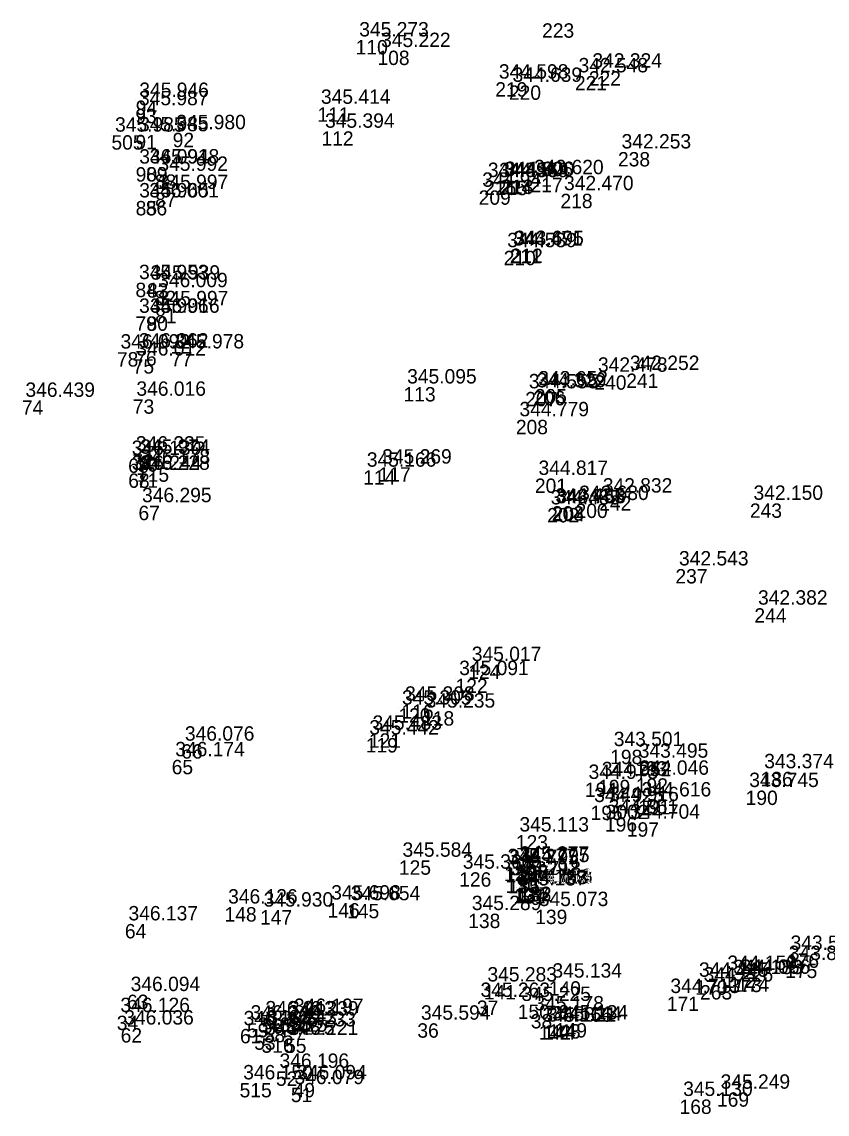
# Model space of a CAD drawing. Extents: x -829398 to -819400, y -1074439 to -1067977.
# Drawn here: x -820131.9 to -820064.8, y -1073098.9 to -1073007.8 of the extents above; entities that cross this region are included whole.
import ezdxf

# ---------------------------------------------------------------- set-up
doc = ezdxf.new("R2010")
doc.units = 0
doc.layers.add('Vrstva 60', color=7, linetype='Continuous')
doc.layers.add('Vrstva 61', color=7, linetype='Continuous')

msp = doc.modelspace()

# ---------------------------------------------------------------- linework, layer by layer
at = {"layer": 'Vrstva 60'}
for p, q in [((-820088.534, -1073007.916), (-820088.534, -1073007.916)), ((-820104.087, -1073009.31), (-820104.087, -1073009.31)), ((-820102.266, -1073010.196), (-820102.266, -1073010.196)), ((-820085.791, -1073012.306), (-820085.791, -1073012.306)), ((-820084.637, -1073011.912), (-820084.637, -1073011.912)), ((-820092.439, -1073012.828), (-820092.439, -1073012.828)), ((-820091.299, -1073013.099), (-820091.299, -1073013.099)), ((-820122.464, -1073015.051), (-820122.464, -1073015.051)), ((-820122.435, -1073014.36), (-820122.435, -1073014.36)), ((-820107.283, -1073014.933), (-820107.283, -1073014.933)), ((-820119.351, -1073017.052), (-820119.351, -1073017.052)), ((-820106.94, -1073016.929), (-820106.94, -1073016.929)), ((-820124.459, -1073017.256), (-820124.459, -1073017.256)), ((-820122.459, -1073017.222), (-820122.459, -1073017.222)), ((-820082.202, -1073018.659), (-820082.202, -1073018.659)), ((-820122.439, -1073019.92), (-820122.439, -1073019.92)), ((-820121.569, -1073019.908), (-820121.569, -1073019.908)), ((-820120.842, -1073020.525), (-820120.842, -1073020.525)), ((-820093.358, -1073021.04), (-820093.358, -1073021.04)), ((-820092.418, -1073021.054), (-820092.418, -1073021.054)), ((-820092.039, -1073020.982), (-820092.039, -1073020.982)), ((-820091.941, -1073020.954), (-820091.941, -1073020.954)), ((-820089.499, -1073020.805), (-820089.499, -1073020.805)), ((-820120.821, -1073022.039), (-820120.821, -1073022.039)), ((-820093.824, -1073021.855), (-820093.824, -1073021.855)), ((-820087.003, -1073022.14), (-820087.003, -1073022.14)), ((-820122.442, -1073022.741), (-820122.442, -1073022.741)), ((-820121.598, -1073022.742), (-820121.598, -1073022.742)), ((-820091.738, -1073026.897), (-820091.738, -1073026.897)), ((-820091.246, -1073026.756), (-820091.246, -1073026.756)), ((-820091.155, -1073026.717), (-820091.155, -1073026.717)), ((-820122.456, -1073029.56), (-820122.456, -1073029.56)), ((-820121.496, -1073029.606), (-820121.496, -1073029.606)), ((-820120.86, -1073030.233), (-820120.86, -1073030.233)), ((-820122.455, -1073032.374), (-820122.455, -1073032.374)), ((-820121.534, -1073032.37), (-820121.534, -1073032.37)), ((-820120.811, -1073031.742), (-820120.811, -1073031.742)), ((-820122.472, -1073035.272), (-820122.472, -1073035.272)), ((-820124.003, -1073035.356), (-820124.003, -1073035.356)), ((-820122.686, -1073035.943), (-820122.686, -1073035.943)), ((-820119.496, -1073035.342), (-820119.496, -1073035.342)), ((-820084.172, -1073037.288), (-820084.172, -1073037.288)), ((-820081.51, -1073037.143), (-820081.51, -1073037.143)), ((-820100.092, -1073038.27), (-820100.092, -1073038.27)), ((-820089.94, -1073038.673), (-820089.94, -1073038.673)), ((-820089.28, -1073038.592), (-820089.28, -1073038.592)), ((-820089.148, -1073038.431), (-820089.148, -1073038.431)), ((-820131.935, -1073039.384), (-820131.935, -1073039.384)), ((-820122.678, -1073039.295), (-820122.678, -1073039.295)), ((-820090.721, -1073041.003), (-820090.721, -1073041.003)), ((-820123.069, -1073044.227), (-820123.069, -1073044.227)), ((-820122.722, -1073043.867), (-820122.722, -1073043.867)), ((-820122.358, -1073044.13), (-820122.358, -1073044.13)), ((-820122.327, -1073044.972), (-820122.327, -1073044.972)), ((-820103.456, -1073045.213), (-820103.456, -1073045.213)), ((-820102.171, -1073044.953), (-820102.171, -1073044.953)), ((-820123.06, -1073045.476), (-820123.06, -1073045.476)), ((-820122.356, -1073045.475), (-820122.356, -1073045.475)), ((-820089.133, -1073045.899), (-820089.133, -1073045.899)), ((-820085.74, -1073047.993), (-820085.74, -1073047.993)), ((-820083.769, -1073047.37), (-820083.769, -1073047.37)), ((-820071.197, -1073047.978), (-820071.197, -1073047.978)), ((-820122.207, -1073048.175), (-820122.207, -1073048.175)), ((-820088.114, -1073048.36), (-820088.114, -1073048.36)), ((-820087.72, -1073048.21), (-820087.72, -1073048.21)), ((-820087.657, -1073048.267), (-820087.657, -1073048.267)), ((-820077.411, -1073053.454), (-820077.411, -1073053.454)), ((-820070.819, -1073056.724), (-820070.819, -1073056.724)), ((-820094.697, -1073061.429), (-820094.697, -1073061.429)), ((-820095.749, -1073062.6), (-820095.749, -1073062.6)), ((-820100.522, -1073065.066), (-820100.522, -1073065.066)), ((-820100.26, -1073064.741), (-820100.26, -1073064.741)), ((-820098.545, -1073065.316), (-820098.545, -1073065.316)), ((-820102.981, -1073067.165), (-820102.981, -1073067.165)), ((-820118.634, -1073068.073), (-820118.634, -1073068.073)), ((-820103.246, -1073067.56), (-820103.246, -1073067.56)), ((-820082.855, -1073068.529), (-820082.855, -1073068.529)), ((-820119.436, -1073069.375), (-820119.436, -1073069.375)), ((-820080.769, -1073069.494), (-820080.769, -1073069.494)), ((-820070.301, -1073070.374), (-820070.301, -1073070.374)), ((-820064.828, -1073070.576), (-820064.828, -1073070.576)), ((-820084.957, -1073071.265), (-820084.957, -1073071.265)), ((-820083.854, -1073071.037), (-820083.854, -1073071.037)), ((-820080.713, -1073070.917), (-820080.713, -1073070.917)), ((-820071.552, -1073071.942), (-820071.552, -1073071.942)), ((-820084.49, -1073073.198), (-820084.49, -1073073.198)), ((-820083.226, -1073073.12), (-820083.226, -1073073.12)), ((-820080.527, -1073072.727), (-820080.527, -1073072.727)), ((-820083.286, -1073074.159), (-820083.286, -1073074.159)), ((-820081.464, -1073074.585), (-820081.464, -1073074.585)), ((-820090.722, -1073075.654), (-820090.722, -1073075.654)), ((-820100.478, -1073077.761), (-820100.478, -1073077.761)), ((-820090.706, -1073078.091), (-820090.706, -1073078.091)), ((-820095.451, -1073078.757), (-820095.451, -1073078.757)), ((-820091.711, -1073078.294), (-820091.711, -1073078.294)), ((-820091.57, -1073078.382), (-820091.57, -1073078.382)), ((-820090.679, -1073078.211), (-820090.679, -1073078.211)), ((-820091.571, -1073079.289), (-820091.571, -1073079.289)), ((-820091.402, -1073079.304), (-820091.402, -1073079.304)), ((-820090.44, -1073079.957), (-820090.44, -1073079.957)), ((-820090.924, -1073080.157), (-820090.924, -1073080.157)), ((-820090.839, -1073080.052), (-820090.839, -1073080.052)), ((-820090.634, -1073079.999), (-820090.634, -1073079.999)), ((-820090.425, -1073079.988), (-820090.425, -1073079.988)), ((-820115.026, -1073081.665), (-820115.026, -1073081.665)), ((-820106.427, -1073081.332), (-820106.427, -1073081.332)), ((-820104.797, -1073081.391), (-820104.797, -1073081.391)), ((-820112.064, -1073081.917), (-820112.064, -1073081.917)), ((-820094.695, -1073082.211), (-820094.695, -1073082.211)), ((-820089.108, -1073081.877), (-820089.108, -1073081.877)), ((-820123.339, -1073083.071), (-820123.339, -1073083.071)), ((-820068.105, -1073085.533), (-820068.105, -1073085.533)), ((-820073.379, -1073087.207), (-820073.379, -1073087.207)), ((-820068.25, -1073086.38), (-820068.25, -1073086.38)), ((-820087.971, -1073087.848), (-820087.971, -1073087.848)), ((-820075.747, -1073087.775), (-820075.747, -1073087.775)), ((-820072.889, -1073087.553), (-820072.889, -1073087.553)), ((-820072.272, -1073087.527), (-820072.272, -1073087.527)), ((-820123.159, -1073088.969), (-820123.159, -1073088.969)), ((-820093.394, -1073088.168), (-820093.394, -1073088.168)), ((-820075.356, -1073088.174), (-820075.356, -1073088.174)), ((-820093.972, -1073089.456), (-820093.972, -1073089.456)), ((-820090.565, -1073089.792), (-820090.565, -1073089.792)), ((-820078.128, -1073089.131), (-820078.128, -1073089.131)), ((-820124.016, -1073090.724), (-820124.016, -1073090.724)), ((-820109.532, -1073090.795), (-820109.532, -1073090.795)), ((-820089.476, -1073090.582), (-820089.476, -1073090.582)), ((-820123.691, -1073091.763), (-820123.691, -1073091.763)), ((-820113.153, -1073091.347), (-820113.153, -1073091.347)), ((-820111.911, -1073090.998), (-820111.911, -1073090.998)), ((-820111.758, -1073091.741), (-820111.758, -1073091.741)), ((-820109.948, -1073091.01), (-820109.948, -1073091.01)), ((-820098.939, -1073091.358), (-820098.939, -1073091.358)), ((-820088.795, -1073091.526), (-820088.795, -1073091.526)), ((-820088.432, -1073091.519), (-820088.432, -1073091.519)), ((-820087.992, -1073091.431), (-820087.992, -1073091.431)), ((-820087.466, -1073091.34), (-820087.466, -1073091.34)), ((-820113.738, -1073091.827), (-820113.738, -1073091.827)), ((-820112.553, -1073092.369), (-820112.553, -1073092.369)), ((-820111.94, -1073092.62), (-820111.94, -1073092.62)), ((-820110.175, -1073091.917), (-820110.175, -1073091.917)), ((-820109.977, -1073092.632), (-820109.977, -1073092.632)), ((-820110.736, -1073095.376), (-820110.736, -1073095.376)), ((-820113.767, -1073096.336), (-820113.767, -1073096.336)), ((-820109.263, -1073096.334), (-820109.263, -1073096.334)), ((-820109.49, -1073096.734), (-820109.49, -1073096.734)), ((-820073.942, -1073097.118), (-820073.942, -1073097.118)), ((-820077.065, -1073097.722), (-820077.065, -1073097.722))]:
    msp.add_line(p, q, dxfattribs=at)

# ---------------------------------------------------------------- texts
for s, p in [('223', (-820088.534, -1073009.116)), ('110', (-820104.087, -1073010.51)), ('108', (-820102.266, -1073011.396)), ('221', (-820085.791, -1073013.506)), ('222', (-820084.637, -1073013.112)), ('219', (-820092.439, -1073014.028)), ('220', (-820091.299, -1073014.299)), ('93', (-820122.464, -1073016.251)), ('94', (-820122.435, -1073015.56)), ('111', (-820107.283, -1073016.133)), ('92', (-820119.351, -1073018.252)), ('112', (-820106.94, -1073018.129)), ('505', (-820124.459, -1073018.456)), ('91', (-820122.459, -1073018.422)), ('238', (-820082.202, -1073019.859)), ('90', (-820122.439, -1073021.12)), ('89', (-820121.569, -1073021.108)), ('88', (-820120.842, -1073021.725)), ('216', (-820093.358, -1073022.24)), ('215', (-820092.418, -1073022.254)), ('214', (-820092.039, -1073022.182)), ('213', (-820091.941, -1073022.154)), ('217', (-820089.499, -1073022.005)), ('87', (-820120.821, -1073023.239)), ('209', (-820093.824, -1073023.055)), ('218', (-820087.003, -1073023.34)), ('85', (-820122.442, -1073023.941)), ('86', (-820121.598, -1073023.942)), ('210', (-820091.738, -1073028.097)), ('211', (-820091.246, -1073027.956)), ('212', (-820091.155, -1073027.917)), ('84', (-820122.456, -1073030.76)), ('83', (-820121.496, -1073030.806)), ('82', (-820120.86, -1073031.433)), ('79', (-820122.455, -1073033.574)), ('80', (-820121.534, -1073033.57)), ('81', (-820120.811, -1073032.942)), ('76', (-820122.472, -1073036.472)), ('78', (-820124.003, -1073036.556)), ('75', (-820122.686, -1073037.143)), ('77', (-820119.496, -1073036.542)), ('240', (-820084.172, -1073038.488)), ('241', (-820081.51, -1073038.343)), ('113', (-820100.092, -1073039.47)), ('207', (-820089.94, -1073039.873)), ('206', (-820089.28, -1073039.792)), ('205', (-820089.148, -1073039.631)), ('74', (-820131.935, -1073040.584)), ('73', (-820122.678, -1073040.495)), ('208', (-820090.721, -1073042.203)), ('69', (-820123.069, -1073045.427)), ('72', (-820122.722, -1073045.067)), ('70', (-820122.358, -1073045.33)), ('115', (-820122.327, -1073046.172)), ('114', (-820103.456, -1073046.413)), ('117', (-820102.171, -1073046.153)), ('68', (-820123.06, -1073046.676)), ('71', (-820122.356, -1073046.675)), ('201', (-820089.133, -1073047.099)), ('200', (-820085.74, -1073049.193)), ('242', (-820083.769, -1073048.57)), ('243', (-820071.197, -1073049.178)), ('67', (-820122.207, -1073049.375)), ('202', (-820088.114, -1073049.56)), ('203', (-820087.72, -1073049.41)), ('204', (-820087.657, -1073049.467)), ('237', (-820077.411, -1073054.654)), ('244', (-820070.819, -1073057.924)), ('124', (-820094.697, -1073062.629)), ('122', (-820095.749, -1073063.8)), ('120', (-820100.522, -1073066.266)), ('116', (-820100.26, -1073065.941)), ('118', (-820098.545, -1073066.516)), ('121', (-820102.981, -1073068.365)), ('66', (-820118.634, -1073069.273)), ('119', (-820103.246, -1073068.76)), ('198', (-820082.855, -1073069.729)), ('65', (-820119.436, -1073070.575)), ('193', (-820080.769, -1073070.694)), ('186', (-820070.301, -1073071.574)), ('194', (-820084.957, -1073072.465)), ('199', (-820083.854, -1073072.237)), ('192', (-820080.713, -1073072.117)), ('190', (-820071.552, -1073073.142)), ('195', (-820084.49, -1073074.398)), ('3002', (-820083.226, -1073074.32)), ('191', (-820080.527, -1073073.927)), ('196', (-820083.286, -1073075.359)), ('197', (-820081.464, -1073075.785)), ('123', (-820090.722, -1073076.854)), ('125', (-820100.478, -1073078.961)), ('128', (-820090.706, -1073079.291)), ('126', (-820095.451, -1073079.957)), ('129', (-820091.711, -1073079.494)), ('136', (-820091.57, -1073079.582)), ('137', (-820090.679, -1073079.411)), ('130', (-820091.571, -1073080.489)), ('135', (-820091.402, -1073080.504)), ('133', (-820090.44, -1073081.157)), ('131', (-820090.924, -1073081.357)), ('134', (-820090.839, -1073081.252)), ('127', (-820090.634, -1073081.199)), ('132', (-820090.425, -1073081.188)), ('148', (-820115.026, -1073082.865)), ('146', (-820106.427, -1073082.532)), ('145', (-820104.797, -1073082.591)), ('147', (-820112.064, -1073083.117)), ('138', (-820094.695, -1073083.411)), ('139', (-820089.108, -1073083.077)), ('64', (-820123.339, -1073084.271)), ('176', (-820068.105, -1073086.733)), ('172', (-820073.379, -1073088.407)), ('175', (-820068.25, -1073087.58)), ('140', (-820087.971, -1073089.048)), ('170', (-820075.747, -1073088.975)), ('263', (-820075.356, -1073089.374)), ('173', (-820072.889, -1073088.753)), ('174', (-820072.272, -1073088.727)), ('63', (-820123.159, -1073090.169)), ('141', (-820093.394, -1073089.368)), ('37', (-820093.972, -1073090.656)), ('150', (-820090.565, -1073090.992)), ('171', (-820078.128, -1073090.331)), ('34', (-820124.016, -1073091.924)), ('33', (-820109.532, -1073091.995)), ('38', (-820089.476, -1073091.782)), ('62', (-820123.691, -1073092.963)), ('61', (-820113.738, -1073093.027)), ('59', (-820113.153, -1073092.547)), ('56', (-820111.911, -1073092.198)), ('58', (-820111.758, -1073092.941)), ('54', (-820109.948, -1073092.21)), ('36', (-820098.939, -1073092.558)), ('142', (-820088.795, -1073092.726)), ('144', (-820088.432, -1073092.719)), ('143', (-820087.992, -1073092.631)), ('149', (-820087.466, -1073092.54)), ('53', (-820112.553, -1073093.569)), ('516', (-820111.94, -1073093.82)), ('57', (-820110.175, -1073093.117)), ('55', (-820109.977, -1073093.832)), ('52', (-820110.736, -1073096.576)), ('515', (-820113.767, -1073097.536)), ('49', (-820109.263, -1073097.534)), ('51', (-820109.49, -1073097.934)), ('169', (-820073.942, -1073098.318)), ('168', (-820077.065, -1073098.922))]:
    msp.add_text(s, height=1.2, dxfattribs=at).set_placement(p)
at = {"layer": 'Vrstva 61'}
for s, p in [('345.273', (-820103.787, -1073009.01)), ('345.222', (-820101.966, -1073009.896)), ('342.324', (-820084.337, -1073011.612)), ('344.598', (-820092.139, -1073012.528)), ('344.639', (-820090.999, -1073012.799)), ('342.548', (-820085.491, -1073012.006)), ('345.946', (-820122.135, -1073014.06)), ('345.414', (-820106.983, -1073014.633)), ('345.987', (-820122.164, -1073014.751)), ('345.985', (-820124.159, -1073016.956)), ('345.985', (-820122.159, -1073016.922)), ('345.980', (-820119.051, -1073016.752)), ('345.394', (-820106.64, -1073016.629)), ('342.253', (-820081.902, -1073018.359)), ('346.094', (-820122.139, -1073019.62)), ('345.918', (-820121.269, -1073019.608)), ('345.992', (-820120.542, -1073020.225)), ('344.896', (-820093.058, -1073020.74)), ('344.569', (-820092.118, -1073020.754)), ('344.506', (-820091.739, -1073020.682)), ('344.000', (-820091.641, -1073020.654)), ('342.620', (-820089.199, -1073020.505)), ('345.997', (-820120.521, -1073021.739)), ('344.941', (-820093.524, -1073021.555)), ('342.470', (-820086.703, -1073021.84)), ('345.965', (-820122.142, -1073022.441)), ('346.001', (-820121.298, -1073022.442)), ('344.471', (-820090.946, -1073026.456)), ('343.695', (-820090.855, -1073026.417)), ('344.539', (-820091.438, -1073026.597)), ('345.953', (-820122.156, -1073029.26)), ('345.939', (-820121.196, -1073029.306)), ('346.009', (-820120.56, -1073029.933)), ('345.997', (-820120.511, -1073031.442)), ('345.996', (-820122.155, -1073032.074)), ('346.016', (-820121.234, -1073032.07)), ('346.092', (-820123.703, -1073035.056)), ('346.062', (-820122.172, -1073034.972)), ('345.978', (-820119.196, -1073035.042)), ('346.012', (-820122.386, -1073035.643)), ('342.478', (-820083.872, -1073036.988)), ('342.252', (-820081.21, -1073036.843)), ('345.095', (-820099.792, -1073037.97)), ('344.329', (-820088.98, -1073038.292)), ('343.652', (-820088.848, -1073038.131)), ('346.439', (-820131.635, -1073039.084)), ('346.016', (-820122.378, -1073038.995)), ('344.555', (-820089.64, -1073038.373)), ('344.779', (-820090.421, -1073040.703)), ('346.235', (-820122.422, -1073043.567)), ('346.130', (-820122.769, -1073043.927)), ('345.974', (-820122.058, -1073043.83)), ('346.178', (-820122.027, -1073044.672)), ('345.269', (-820101.871, -1073044.653)), ('346.244', (-820122.76, -1073045.176)), ('346.228', (-820122.056, -1073045.175)), ('345.166', (-820103.156, -1073044.913)), ('344.817', (-820088.833, -1073045.599)), ('342.832', (-820083.469, -1073047.07)), ('346.295', (-820121.907, -1073047.875)), ('344.485', (-820087.814, -1073048.06)), ('344.455', (-820087.42, -1073047.91)), ('343.753', (-820087.357, -1073047.967)), ('342.680', (-820085.44, -1073047.693)), ('342.150', (-820070.897, -1073047.678)), ('342.543', (-820077.111, -1073053.154)), ('342.382', (-820070.519, -1073056.424)), ('345.017', (-820094.397, -1073061.129)), ('345.091', (-820095.449, -1073062.3)), ('345.305', (-820100.222, -1073064.766)), ('345.308', (-820099.96, -1073064.441)), ('345.235', (-820098.245, -1073065.016)), ('345.442', (-820102.946, -1073067.26)), ('345.483', (-820102.681, -1073066.865)), ('346.076', (-820118.334, -1073067.773)), ('343.501', (-820082.555, -1073068.229)), ('346.174', (-820119.136, -1073069.075)), ('343.495', (-820080.469, -1073069.194)), ('343.374', (-820070.001, -1073070.074)), ('344.973', (-820084.657, -1073070.965)), ('344.952', (-820083.554, -1073070.737)), ('344.046', (-820080.413, -1073070.617)), ('343.745', (-820071.252, -1073071.642)), ('344.925', (-820084.19, -1073072.898)), ('344.916', (-820082.926, -1073072.82)), ('344.616', (-820080.227, -1073072.427)), ('344.851', (-820082.986, -1073073.859)), ('344.704', (-820081.164, -1073074.285)), ('345.113', (-820090.422, -1073075.354)), ('345.584', (-820100.178, -1073077.461)), ('345.277', (-820091.411, -1073077.994)), ('344.795', (-820091.27, -1073078.082)), ('345.277', (-820090.406, -1073077.791)), ('344.795', (-820090.379, -1073077.911)), ('345.360', (-820095.151, -1073078.457)), ('345.292', (-820091.271, -1073078.989)), ('344.718', (-820091.102, -1073079.004)), ('345.137', (-820090.624, -1073079.857)), ('344.763', (-820090.539, -1073079.752)), ('344.744', (-820090.334, -1073079.699)), ('344.752', (-820090.14, -1073079.657)), ('345.116', (-820090.125, -1073079.688)), ('345.698', (-820106.127, -1073081.032)), ('345.654', (-820104.497, -1073081.091)), ('346.126', (-820114.726, -1073081.365)), ('345.930', (-820111.764, -1073081.617)), ('345.289', (-820094.395, -1073081.911)), ('345.073', (-820088.808, -1073081.577)), ('346.137', (-820123.039, -1073082.771)), ('343.593', (-820067.805, -1073085.233)), ('343.823', (-820067.95, -1073086.08)), ('345.134', (-820087.671, -1073087.548)), ('344.445', (-820075.447, -1073087.475)), ('344.150', (-820073.079, -1073086.907)), ('344.183', (-820072.589, -1073087.253)), ('344.066', (-820071.972, -1073087.227)), ('345.283', (-820093.094, -1073087.868)), ('344.226', (-820075.056, -1073087.874)), ('346.094', (-820122.859, -1073088.669)), ('345.263', (-820093.672, -1073089.156)), ('344.713', (-820077.828, -1073088.831)), ('345.225', (-820090.265, -1073089.492)), ('345.178', (-820089.176, -1073090.282)), ('346.126', (-820123.716, -1073090.424)), ('346.246', (-820112.853, -1073091.047)), ('346.243', (-820111.611, -1073090.698)), ('346.239', (-820109.648, -1073090.71)), ('346.197', (-820109.232, -1073090.495)), ('345.594', (-820098.639, -1073091.058)), ('345.144', (-820087.692, -1073091.131)), ('345.134', (-820087.166, -1073091.04)), ('346.036', (-820123.391, -1073091.463)), ('346.284', (-820113.438, -1073091.527)), ('346.125', (-820112.253, -1073092.069)), ('346.243', (-820111.458, -1073091.441)), ('346.233', (-820109.875, -1073091.617)), ('345.166', (-820088.495, -1073091.226)), ('344.821', (-820088.132, -1073091.219)), ('346.225', (-820111.64, -1073092.32)), ('346.221', (-820109.677, -1073092.332)), ('346.196', (-820110.436, -1073095.076)), ('346.150', (-820113.467, -1073096.036)), ('346.079', (-820109.19, -1073096.434)), ('346.094', (-820108.963, -1073096.034)), ('345.130', (-820076.765, -1073097.422)), ('345.249', (-820073.642, -1073096.818))]:
    msp.add_text(s, height=1.2, dxfattribs=at).set_placement(p)

doc.saveas('drawing.dxf')
